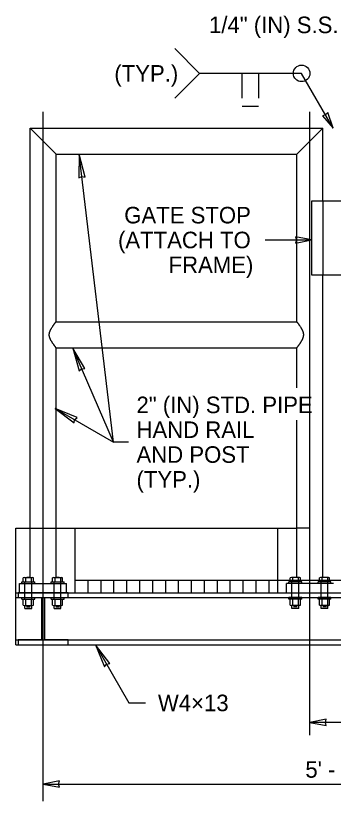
# Model space of a CAD drawing. Extents: x 99862 to 103151, y 100000 to 108076.
# Drawn here: x 102282 to 102590, y 100915 to 101674 of the extents above; entities that cross this region are included whole.
import ezdxf

# ---------------------------------------------------------------- set-up
doc = ezdxf.new("R2010")
doc.units = 0
for name, color, linetype in [('Level 15', 7, 'Continuous'), ('Level 2', 7, 'Continuous'), ('Level 20', 7, 'Continuous'), ('Level 36', 7, 'Continuous'), ('Level 4', 7, 'Continuous')]:
    doc.layers.add(name, color=color, linetype=linetype)

msp = doc.modelspace()

# ---------------------------------------------------------------- linework, layer by layer
at = {"layer": 'Level 15'}
for p, q in [((102589.52, 101565.31), (102558.88, 101618.38)), ((102308.84, 100914.85), (102308.84, 101581.31)), ((102566.83, 100978.9), (102566.83, 101581.31)), ((102376.77, 101261.98), (102343.8, 101540.31)), ((102523.67, 101457.37), (102568.82, 101457.37)), ((102376.77, 101261.98), (102337.45, 101352.96)), ((102320.48, 101294.48), (102376.77, 101261.98)), ((102391.42, 101261.98), (102376.77, 101261.98)), ((102359.38, 101066.22), (102391.88, 101009.93)), ((102391.88, 101009.93), (102407.88, 101009.93)), ((102866.83, 100991.1), (102566.83, 100991.1)), ((102308.84, 100931.49), (102866.84, 100931.49))]:
    msp.add_line(p, q, dxfattribs=at)
for points in [[(102589.52, 101565.31), (102584.33, 101580.47), (102582.03, 101578.3), (102578.99, 101577.39)], [(102343.8, 101540.31), (102343.52, 101517.29), (102346.36, 101518.69), (102349.45, 101517.99)], [(102568.82, 101457.37), (102553.1, 101460.45), (102553.82, 101457.37), (102553.1, 101454.29)], [(102337.45, 101352.96), (102343.75, 101330.81), (102346.07, 101332.96), (102349.23, 101333.18)], [(102320.48, 101294.49), (102338.76, 101280.49), (102339.34, 101283.6), (102341.74, 101285.66)], [(102359.38, 101066.22), (102368.21, 101044.96), (102370.26, 101047.37), (102373.38, 101047.95)], [(102566.83, 100991.1), (102582.56, 100988.01), (102581.83, 100991.1), (102582.56, 100994.18)], [(102308.83, 100931.49), (102324.56, 100928.41), (102323.83, 100931.49), (102324.56, 100934.58)]]:
    msp.add_lwpolyline(points, close=True, dxfattribs=at)
at = {"layer": 'Level 2'}
for p, q in [((102296.34, 101565.31), (102321.34, 101540.31)), ((102579.33, 101565.31), (102554.34, 101540.31))]:
    msp.add_line(p, q, dxfattribs=at)
for points in [[(102321.33, 101353.24), (102321.33, 101353.24), (102321.33, 101353.24), (102321.33, 101353.24), (102321.32, 101353.24), (102321.27, 101353.32), (102321.17, 101353.45), (102321.04, 101353.6), (102320.98, 101353.7), (102320.96, 101353.72), (102320.91, 101353.78), (102320.79, 101353.93), (102320.53, 101354.28), (102320.24, 101354.66), (102320.01, 101354.97), (102319.94, 101355.07), (102319.78, 101355.28), (102319.53, 101355.61), (102319.08, 101356.22), (102318.61, 101356.88), (102318.32, 101357.31), (102318.13, 101357.59), (102318.03, 101357.74), (102317.74, 101358.2), (102317.33, 101358.81), (102316.94, 101359.44), (102316.54, 101360.13), (102316.35, 101360.48), (102316.07, 101361.02), (102315.99, 101361.19), (102315.81, 101361.58), (102315.72, 101361.75), (102315.48, 101362.34), (102315.32, 101362.74), (102315.17, 101363.25), (102315.13, 101363.35), (102315.07, 101363.56), (102315.04, 101363.66), (102314.97, 101363.99), (102314.88, 101364.42), (102314.83, 101364.85), (102314.79, 101365.29), (102314.78, 101365.51), (102314.78, 101365.74), (102314.78, 101366.2), (102314.82, 101366.63), (102314.93, 101367.27), (102314.99, 101367.6), (102315.07, 101367.9), (102315.13, 101368.13), (102315.16, 101368.23), (102315.32, 101368.74), (102315.48, 101369.15), (102315.81, 101369.91), (102315.97, 101370.26), (102316.25, 101370.82), (102316.35, 101371), (102316.54, 101371.33), (102316.84, 101371.87), (102317.33, 101372.68), (102317.93, 101373.59), (102318.41, 101374.31), (102318.79, 101374.84), (102318.98, 101375.12), (102319.26, 101375.5), (102319.61, 101375.98), (102320.01, 101376.52), (102320.27, 101376.85), (102320.37, 101377), (102320.44, 101377.07), (102320.47, 101377.13), (102320.63, 101377.35), (102320.86, 101377.63), (102321.09, 101377.94), (102321.18, 101378.04), (102321.23, 101378.12), (102321.26, 101378.14), (102321.32, 101378.22), (102321.33, 101378.24), (102321.33, 101378.24), (102321.33, 101378.24)], [(102554.33, 101353.24), (102554.33, 101353.24), (102554.33, 101353.24), (102554.33, 101353.24), (102554.35, 101353.24), (102554.4, 101353.32), (102554.5, 101353.45), (102554.62, 101353.6), (102554.69, 101353.7), (102554.7, 101353.72), (102554.75, 101353.78), (102554.88, 101353.93), (102555.13, 101354.28), (102555.43, 101354.66), (102555.65, 101354.97), (102555.73, 101355.07), (102555.88, 101355.28), (102556.14, 101355.61), (102556.58, 101356.22), (102557.05, 101356.88), (102557.34, 101357.31), (102557.53, 101357.59), (102557.64, 101357.74), (102557.93, 101358.2), (102558.33, 101358.81), (102558.73, 101359.44), (102559.12, 101360.13), (102559.31, 101360.48), (102559.59, 101361.02), (102559.68, 101361.19), (102559.86, 101361.58), (102559.95, 101361.75), (102560.19, 101362.34), (102560.34, 101362.74), (102560.49, 101363.25), (102560.53, 101363.35), (102560.6, 101363.56), (102560.62, 101363.66), (102560.7, 101363.99), (102560.79, 101364.42), (102560.84, 101364.85), (102560.88, 101365.29), (102560.89, 101365.51), (102560.89, 101365.74), (102560.89, 101366.2), (102560.85, 101366.63), (102560.74, 101367.27), (102560.67, 101367.6), (102560.6, 101367.9), (102560.53, 101368.13), (102560.51, 101368.23), (102560.34, 101368.74), (102560.19, 101369.15), (102559.86, 101369.91), (102559.69, 101370.26), (102559.42, 101370.82), (102559.31, 101371), (102559.12, 101371.33), (102558.83, 101371.87), (102558.33, 101372.68), (102557.74, 101373.59), (102557.26, 101374.31), (102556.87, 101374.84), (102556.68, 101375.12), (102556.4, 101375.5), (102556.06, 101375.98), (102555.65, 101376.52), (102555.4, 101376.85), (102555.3, 101377), (102555.22, 101377.07), (102555.2, 101377.13), (102555.03, 101377.35), (102554.8, 101377.63), (102554.57, 101377.94), (102554.49, 101378.04), (102554.43, 101378.12), (102554.41, 101378.14), (102554.35, 101378.22), (102554.33, 101378.24), (102554.33, 101378.24), (102554.33, 101378.24)]]:
    msp.add_open_spline(points, degree=3, dxfattribs=at)
at = {"layer": 'Level 20'}
for p, q in [((102436.18, 101642.38), (102460.18, 101618.38)), ((102436.18, 101594.38), (102460.18, 101618.38)), ((102558.88, 101618.38), (102460.18, 101618.38)), ((102501.23, 101594.38), (102501.23, 101618.38)), ((102517.23, 101618.38), (102517.23, 101594.38)), ((102517.23, 101586.38), (102501.23, 101586.38))]:
    msp.add_line(p, q, dxfattribs=at)
msp.add_circle((102558.88, 101618.38), 8, dxfattribs=at)
at = {"layer": 'Level 36'}
for p, q in [((102579.33, 101495.34), (102579.33, 101423.21)), ((102296.34, 101178.72), (102321.34, 101178.72)), ((102566.83, 101178.72), (102554.34, 101178.72)), ((102284.6, 101111.67), (102307.32, 101111.67)), ((102307.32, 101111.67), (102307.32, 101070.77)), ((102310.35, 101070.77), (102310.35, 101111.67)), ((102310.35, 101111.67), (102333.08, 101111.67)), ((102307.32, 101070.77), (102284.6, 101070.77)), ((102333.08, 101070.77), (102310.35, 101070.77))]:
    msp.add_line(p, q, dxfattribs=at)
for points in [[(102333.08, 101111.67), (102333.08, 101116.22), (102284.6, 101116.22), (102284.6, 101111.67)], [(102284.6, 101070.77), (102284.6, 101066.22), (102333.08, 101066.22), (102333.08, 101070.77)]]:
    msp.add_lwpolyline(points, dxfattribs=at)
at = {"layer": 'Level 4'}
for p, q in [((102296.34, 101131.15), (102296.34, 101565.31)), ((102296.34, 101565.31), (102579.33, 101565.31)), ((102579.33, 101495.34), (102579.33, 101565.31)), ((102321.34, 101378.24), (102321.34, 101540.31)), ((102321.34, 101540.31), (102554.34, 101540.31)), ((102554.34, 101378.24), (102554.34, 101540.31)), ((102579.33, 101131.15), (102579.33, 101423.21)), ((102321.34, 101378.24), (102554.34, 101378.24)), ((102321.34, 101131.15), (102321.34, 101353.24)), ((102321.34, 101353.24), (102554.34, 101353.24)), ((102554.34, 101314.43), (102554.34, 101353.24)), ((102554.34, 101131.15), (102554.34, 101283.19)), ((102282.32, 101066.22), (102282.32, 101178.72)), ((102282.32, 101178.72), (102296.34, 101178.72)), ((102321.34, 101178.72), (102554.34, 101178.72)), ((102339.89, 101116.22), (102339.89, 101178.72)), ((102535.78, 101116.22), (102535.78, 101178.72)), ((102289.69, 101126.82), (102289.69, 101130.82)), ((102290.7, 101131.15), (102298.4, 101131.15)), ((102291.75, 101130.82), (102291.75, 101126.82)), ((102297.37, 101130.82), (102297.37, 101126.82)), ((102299.43, 101126.82), (102299.43, 101130.82)), ((102317.98, 101126.82), (102317.98, 101130.82)), ((102318.99, 101131.15), (102326.69, 101131.15)), ((102320.04, 101130.82), (102320.04, 101126.82)), ((102325.66, 101130.82), (102325.66, 101126.82)), ((102327.72, 101126.82), (102327.72, 101130.82)), ((102339.89, 101128.72), (102847.95, 101128.72)), ((102352.39, 101116.22), (102352.39, 101128.72)), ((102364.89, 101116.22), (102364.89, 101128.72)), ((102377.39, 101116.22), (102377.39, 101128.72)), ((102389.89, 101116.22), (102389.89, 101128.72)), ((102402.39, 101116.22), (102402.39, 101128.72)), ((102414.89, 101116.22), (102414.89, 101128.72)), ((102427.39, 101116.22), (102427.39, 101128.72)), ((102439.89, 101116.22), (102439.89, 101128.72)), ((102452.39, 101116.22), (102452.39, 101128.72)), ((102464.89, 101116.22), (102464.89, 101128.72)), ((102477.39, 101116.22), (102477.39, 101128.72)), ((102489.89, 101116.22), (102489.89, 101128.72)), ((102502.39, 101116.22), (102502.39, 101128.72)), ((102514.89, 101116.22), (102514.89, 101128.72)), ((102527.39, 101116.22), (102527.39, 101128.72)), ((102547.95, 101126.82), (102547.95, 101130.82)), ((102556.68, 101131.15), (102548.98, 101131.15)), ((102550.01, 101130.82), (102550.01, 101126.82)), ((102555.63, 101130.82), (102555.63, 101126.82)), ((102557.69, 101126.82), (102557.69, 101130.82)), ((102576.24, 101126.82), (102576.24, 101130.82)), ((102584.97, 101131.15), (102577.27, 101131.15)), ((102578.3, 101130.82), (102578.3, 101126.82)), ((102583.92, 101130.82), (102583.92, 101126.82)), ((102585.98, 101126.82), (102585.98, 101130.82)), ((102286.11, 101125.31), (102331.56, 101125.31)), ((102286.11, 101116.22), (102286.11, 101125.31)), ((102288.41, 101126.82), (102300.89, 101126.82)), ((102288.41, 101125.31), (102288.41, 101126.82)), ((102289.69, 101126.82), (102299.43, 101126.82)), ((102291.31, 101110.16), (102291.31, 101126.82)), ((102297.8, 101110.16), (102297.8, 101126.82)), ((102300.89, 101125.31), (102300.89, 101126.82)), ((102316.7, 101126.82), (102329.18, 101126.82)), ((102316.7, 101125.31), (102316.7, 101126.82)), ((102317.98, 101126.82), (102327.72, 101126.82)), ((102319.6, 101110.16), (102319.6, 101126.82)), ((102326.1, 101110.16), (102326.1, 101126.82)), ((102329.18, 101125.31), (102329.18, 101126.82)), ((102331.56, 101116.22), (102331.56, 101125.31)), ((102589.56, 101125.31), (102544.11, 101125.31)), ((102544.11, 101116.22), (102544.11, 101125.31)), ((102558.97, 101126.82), (102546.49, 101126.82)), ((102546.49, 101125.31), (102546.49, 101126.82)), ((102557.69, 101126.82), (102547.95, 101126.82)), ((102549.57, 101110.16), (102549.57, 101126.82)), ((102556.07, 101110.16), (102556.07, 101126.82)), ((102558.97, 101125.31), (102558.97, 101126.82)), ((102587.26, 101126.82), (102574.78, 101126.82)), ((102574.78, 101125.31), (102574.78, 101126.82)), ((102585.98, 101126.82), (102576.24, 101126.82)), ((102577.87, 101110.16), (102577.87, 101126.82)), ((102584.36, 101110.16), (102584.36, 101126.82)), ((102587.26, 101125.31), (102587.26, 101126.82)), ((102282.32, 101116.22), (102985.7, 101116.22)), ((102282.32, 101111.67), (102985.7, 101111.67)), ((102288.41, 101110.16), (102288.41, 101111.67)), ((102288.41, 101111.67), (102300.89, 101111.67)), ((102288.41, 101110.16), (102300.89, 101110.16)), ((102289.69, 101110.16), (102299.43, 101110.16)), ((102289.69, 101104.48), (102289.69, 101110.16)), ((102291.75, 101110.16), (102291.75, 101104.48)), ((102297.37, 101110.16), (102297.37, 101104.48)), ((102299.43, 101104.48), (102299.43, 101110.16)), ((102300.89, 101110.16), (102300.89, 101111.67)), ((102316.7, 101110.16), (102316.7, 101111.67)), ((102316.7, 101111.67), (102329.18, 101111.67)), ((102316.7, 101110.16), (102329.18, 101110.16)), ((102317.98, 101110.16), (102327.72, 101110.16)), ((102317.98, 101104.48), (102317.98, 101110.16)), ((102320.04, 101110.16), (102320.04, 101104.48)), ((102325.66, 101110.16), (102325.66, 101104.48)), ((102327.72, 101104.48), (102327.72, 101110.16)), ((102329.18, 101110.16), (102329.18, 101111.67)), ((102546.49, 101110.16), (102546.49, 101111.67)), ((102558.97, 101111.67), (102546.49, 101111.67)), ((102558.97, 101110.16), (102546.49, 101110.16)), ((102557.69, 101110.16), (102547.95, 101110.16)), ((102547.95, 101104.48), (102547.95, 101110.16)), ((102550.01, 101110.16), (102550.01, 101104.48)), ((102555.63, 101110.16), (102555.63, 101104.48)), ((102557.69, 101104.48), (102557.69, 101110.16)), ((102558.97, 101110.16), (102558.97, 101111.67)), ((102574.78, 101110.16), (102574.78, 101111.67)), ((102587.26, 101111.67), (102574.78, 101111.67)), ((102587.26, 101110.16), (102574.78, 101110.16)), ((102585.98, 101110.16), (102576.24, 101110.16)), ((102576.24, 101104.48), (102576.24, 101110.16)), ((102578.3, 101110.16), (102578.3, 101104.48)), ((102583.92, 101110.16), (102583.92, 101104.48)), ((102585.98, 101104.48), (102585.98, 101110.16)), ((102587.26, 101110.16), (102587.26, 101111.67)), ((102290.7, 101104.15), (102298.4, 101104.15)), ((102291.31, 101101.23), (102291.31, 101104.15)), ((102291.31, 101101.23), (102297.8, 101101.23)), ((102292.82, 101102.74), (102296.29, 101102.74)), ((102297.8, 101101.23), (102297.8, 101104.15)), ((102318.99, 101104.15), (102326.69, 101104.15)), ((102319.6, 101101.23), (102319.6, 101104.15)), ((102319.6, 101101.23), (102326.1, 101101.23)), ((102321.12, 101102.74), (102324.58, 101102.74)), ((102326.1, 101101.23), (102326.1, 101104.15)), ((102556.68, 101104.15), (102548.98, 101104.15)), ((102549.57, 101101.23), (102549.57, 101104.15)), ((102556.07, 101101.23), (102549.57, 101101.23)), ((102554.55, 101102.74), (102551.09, 101102.74)), ((102556.07, 101101.23), (102556.07, 101104.15)), ((102584.97, 101104.15), (102577.27, 101104.15)), ((102577.87, 101101.23), (102577.87, 101104.15)), ((102584.36, 101101.23), (102577.87, 101101.23)), ((102582.85, 101102.74), (102579.38, 101102.74)), ((102584.36, 101101.23), (102584.36, 101104.15)), ((102282.32, 101070.77), (102985.7, 101070.77)), ((102282.32, 101066.22), (102985.7, 101066.22))]:
    msp.add_line(p, q, dxfattribs=at)
msp.add_lwpolyline([(102568.82, 101495.34), (102598.85, 101495.34), (102598.85, 101423.21), (102568.82, 101423.21)], close=True, dxfattribs=at)
for centre, radius, start, end in [((102290.72, 101129.37), 1.78, 54.71987, 125.28013), ((102294.56, 101118.88), 12.27, 76.75036, 103.24964), ((102298.4, 101129.37), 1.78, 54.71987, 125.28013), ((102319.01, 101129.37), 1.78, 54.71987, 125.28013), ((102322.85, 101118.88), 12.27, 76.75036, 103.24964), ((102326.69, 101129.37), 1.78, 54.71987, 125.28013), ((102548.98, 101129.37), 1.78, 54.71987, 125.28013), ((102552.82, 101118.88), 12.27, 76.75036, 103.24964), ((102556.66, 101129.37), 1.78, 54.71987, 125.28013), ((102577.27, 101129.37), 1.78, 54.71987, 125.28013), ((102581.11, 101118.88), 12.27, 76.75036, 103.24964), ((102584.95, 101129.37), 1.78, 54.71987, 125.28013), ((102290.72, 101105.93), 1.78, 234.71987, 305.28013), ((102294.56, 101116.42), 12.27, 256.75036, 283.24964), ((102298.4, 101105.93), 1.78, 234.71987, 305.28013), ((102319.01, 101105.93), 1.78, 234.71987, 305.28013), ((102322.85, 101116.42), 12.27, 256.75036, 283.24964), ((102326.69, 101105.93), 1.78, 234.71987, 305.28013), ((102548.98, 101105.93), 1.78, 234.71987, 305.28013), ((102552.82, 101116.42), 12.27, 256.75036, 283.24964), ((102556.66, 101105.93), 1.78, 234.71987, 305.28013), ((102577.27, 101105.93), 1.78, 234.71987, 305.28013), ((102581.11, 101116.42), 12.27, 256.75036, 283.24964), ((102584.95, 101105.93), 1.78, 234.71987, 305.28013)]:
    msp.add_arc(centre, radius, start, end, dxfattribs=at)

# ---------------------------------------------------------------- texts
at = {"layer": 'Level 20'}
for s, p in [('1/4" (IN) S.S. SCREWS', (102469.31, 101657.27)), ('(TYP.)', (102377.73, 101610.39)), ('GATE STOP', (102387.31, 101473.37)), ('(ATTACH TO', (102381.3, 101449.37)), ('FRAME)', (102430.18, 101425.37)), ('2" (IN) STD. PIPE', (102399.16, 101289.99)), ('HAND RAIL', (102399.16, 101265.99)), ('AND POST', (102399.16, 101241.99)), ('(TYP.)', (102399.16, 101217.99)), ('W4×13', (102419.89, 101001.94)), ('5\' - 0"', (102562.5, 100937.61))]:
    msp.add_text(s, height=16, dxfattribs=at).set_placement(p)

doc.saveas('drawing.dxf')
